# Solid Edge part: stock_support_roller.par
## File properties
Title: Stock support roller
Author: Abhinav Rai
Template: Normal.par
Last saved by: Cadcim
Revision: 12
Application: Solid Edge
Material: aluminum
Density: 0 kg/mm^3
Accuracy: 0.99
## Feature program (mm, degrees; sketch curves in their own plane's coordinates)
sketch for "unnamed RevolvedProtrusion 1" plane through (0, 0, 0) normal (0, -1, 0) x-axis (1, 0, 0)
  line (60, 0) -> (60, 24.638)
  line (60, 24.638) -> (15.55, 24.638)
  line (15.55, 24.638) -> (15.55, 92.075)
  line (15.55, 92.075) -> (-2.2388, 92.075)
  line (-2.2388, 92.075) -> (-111.45, 29.0219)
  line (-220.6612, 92.075) -> (-111.45, 29.0219)
  line (-238.45, 92.075) -> (-220.6612, 92.075)
  line (-238.45, 24.638) -> (-238.45, 92.075)
  line (-282.9, 24.638) -> (-238.45, 24.638)
  line (-282.9, 0) -> (-282.9, 24.638)
revolve "unnamed RevolvedProtrusion 1" add full turn 360 deg about sketch line (-282.9, 0) -> (60, 0)
chamfer "unnamed Chamfer 1"
fillet "Round_1" radius 1.5748
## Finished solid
Body 1: solid body, 14 faces, 13 edges, 0 vertices.
  Faces by surface: cone 4, cylinder 4, plane 4, torus 2
  Edges by curve: circle 13
Bounding box of the edges (mm; curved faces can reach further): 342.900 x 184.150 x 184.150, from (-282.9, -92.075, -92.075) to (60, 92.075, 92.075).
Cylindrical faces by radius (mm): R24.638 x2, R92.075 x2
Conical faces (half-angle, radius in mm at the cone's reference point): 30 deg R29.0219 x1, 30 deg R92.075 x1, 45 deg R23.0632 x1, 45 deg R24.638 x1
Toroidal faces (ring radius, tube radius in mm): R26.2128 r1.5748 x2
Planar faces by outward normal: +x 2, -x 2
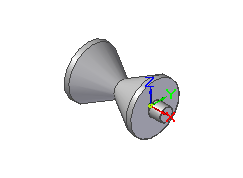
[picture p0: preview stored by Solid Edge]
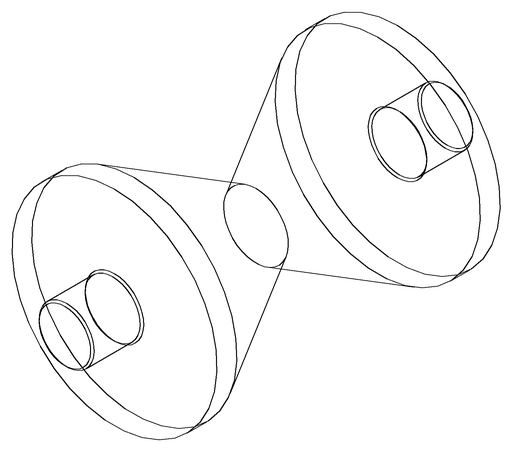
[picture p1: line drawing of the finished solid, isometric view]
